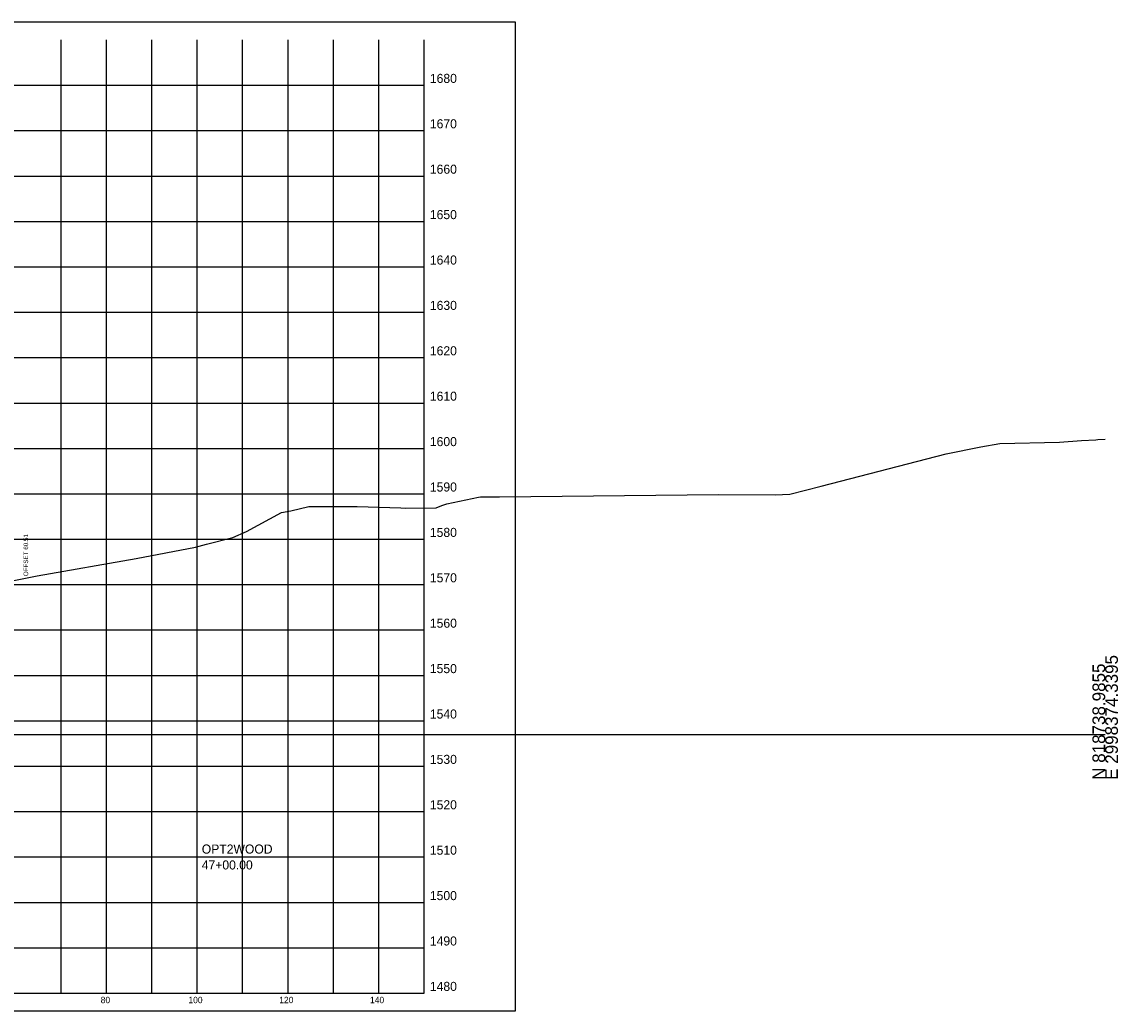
# Model space of a CAD drawing. Extents: x -26 to 2998798, y -429 to 819149.
# Drawn here: x 361.4 to 602.8, y 2439.1 to 2656.9 of the extents above; entities that cross this region are included whole.
import ezdxf

# ---------------------------------------------------------------- set-up
doc = ezdxf.new("R2010")
doc.units = 0
for name, color, linetype in [('DESIGN - SHEET - Corner Text', 7, 'Continuous'), ('DESIGN - SHEET - Light Grid', 7, 'Continuous'), ('DESIGN - SHEET - Linework', 7, 'Continuous'), ('DESIGN - SHEET - Plot Shape', 7, 'Continuous'), ('DESIGN - TYPICAL - Slope Tie Text', 7, 'Continuous'), ('DESIGN - TYPICAL - Warning Text', 7, 'Continuous'), ('SURVEY - GROUND - Top of Ground', 7, 'Continuous')]:
    doc.layers.add(name, color=color, linetype=linetype)

msp = doc.modelspace()

# ---------------------------------------------------------------- linework, layer by layer
at = {"layer": 'DESIGN - SHEET - Light Grid'}
msp.add_line((300, 2500), (600, 2500), dxfattribs=at)
at = {"layer": 'DESIGN - SHEET - Linework'}
for p, q in [((370, 2443), (370, 2653)), ((380, 2443), (380, 2653)), ((390, 2443), (390, 2653)), ((400, 2443), (400, 2653)), ((410, 2443), (410, 2653)), ((420, 2443), (420, 2653)), ((430, 2443), (430, 2653)), ((440, 2443), (440, 2653)), ((150, 2643), (450, 2643)), ((150, 2633), (450, 2633)), ((150, 2623), (450, 2623)), ((150, 2613), (450, 2613)), ((150, 2603), (450, 2603)), ((150, 2593), (450, 2593)), ((150, 2583), (450, 2583)), ((150, 2573), (450, 2573)), ((150, 2563), (450, 2563)), ((150, 2553), (450, 2553)), ((150, 2543), (450, 2543)), ((150, 2533), (450, 2533)), ((150, 2523), (450, 2523)), ((150, 2513), (450, 2513)), ((150, 2503), (450, 2503)), ((150, 2493), (450, 2493)), ((150, 2483), (450, 2483)), ((150, 2473), (450, 2473)), ((150, 2463), (450, 2463)), ((150, 2453), (450, 2453))]:
    msp.add_line(p, q, dxfattribs=at)
msp.add_lwpolyline([(150, 2653), (150, 2443), (450, 2443), (450, 2653)], dxfattribs=at)
at = {"layer": 'DESIGN - SHEET - Plot Shape'}
msp.add_lwpolyline([(130, 2656.94), (470, 2656.94), (470, 2439.06), (130, 2439.06)], close=True, dxfattribs=at)
at = {"layer": 'SURVEY - GROUND - Top of Ground'}
msp.add_lwpolyline([(358.52, 2533.65), (364.71, 2534.93), (386.53, 2538.72), (399.63, 2541.24), (402.08, 2541.87), (407.88, 2543.38), (410.83, 2544.72), (418.55, 2548.85), (420.61, 2549.27), (424.55, 2550.2), (427.5, 2550.19), (433.66, 2550.22), (435.21, 2550.17), (444.84, 2549.89), (445.91, 2549.86), (452.64, 2549.94), (453.85, 2550.43), (454.33, 2550.56), (455, 2550.8), (457.74, 2551.38), (461.97, 2552.27), (462.37, 2552.33), (466.62, 2552.36), (514.85, 2552.84), (527.32, 2552.77), (530.56, 2552.9), (537.47, 2554.69), (564.95, 2561.84), (572.59, 2563.33), (576.76, 2564.09), (589.94, 2564.37), (594.75, 2564.71), (597.93, 2564.92), (598.36, 2564.95), (600, 2565.05)], dxfattribs=at)

# ---------------------------------------------------------------- texts
at = {"layer": 'DESIGN - SHEET - Corner Text'}
for s, height, p in [('1680', 2, (451.25, 2643.5)), ('1670', 2, (451.25, 2633.5)), ('1660', 2, (451.25, 2623.5)), ('1650', 2, (451.25, 2613.5)), ('1640', 2, (451.25, 2603.5)), ('1630', 2, (451.25, 2593.5)), ('1620', 2, (451.25, 2583.5)), ('1610', 2, (451.25, 2573.5)), ('1600', 2, (451.25, 2563.5)), ('1590', 2, (451.25, 2553.5)), ('1580', 2, (451.25, 2543.5)), ('1570', 2, (451.25, 2533.5)), ('1560', 2, (451.25, 2523.5)), ('1550', 2, (451.25, 2513.5)), ('1540', 2, (451.25, 2503.5)), ('1530', 2, (451.25, 2493.5)), ('1520', 2, (451.25, 2483.5)), ('1510', 2, (451.25, 2473.5)), ('1500', 2, (451.25, 2463.5)), ('1490', 2, (451.25, 2453.5)), ('1480', 2, (451.25, 2443.5)), ('80', 1.4, (378.74, 2440.8)), ('100', 1.4, (398.06, 2440.8)), ('120', 1.4, (418.06, 2440.8)), ('140', 1.4, (438.06, 2440.8))]:
    msp.add_text(s, height=height, dxfattribs=at).set_placement(p)
at = {"layer": 'DESIGN - SHEET - Light Grid'}
for s, p in [('E 2998374.3395', (602.8, 2490)), ('N 818738.9855', (600, 2490))]:
    msp.add_text(s, height=2.8, rotation=90, dxfattribs=at).set_placement(p)
at = {"layer": 'DESIGN - TYPICAL - Slope Tie Text'}
msp.add_text('OFFSET 60.51', height=1, rotation=90, dxfattribs=at).set_placement((362.76, 2534.85))
at = {"layer": 'DESIGN - TYPICAL - Warning Text'}
for s, p in [('OPT2WOOD', (401, 2473.75)), ('47+00.00', (401, 2470.25))]:
    msp.add_text(s, height=2, dxfattribs=at).set_placement(p)

doc.saveas('drawing.dxf')
